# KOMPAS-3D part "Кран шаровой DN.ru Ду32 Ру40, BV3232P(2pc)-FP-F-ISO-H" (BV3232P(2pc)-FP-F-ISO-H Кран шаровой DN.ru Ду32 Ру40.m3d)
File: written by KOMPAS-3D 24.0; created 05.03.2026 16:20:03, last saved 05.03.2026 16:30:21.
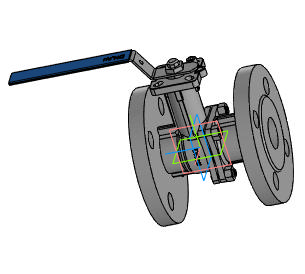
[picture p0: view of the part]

Document properties: Автор: R2D2; Полное имя файла: BV3232P(2pc)-FP-F-ISO-H Кран шаровой DN.ru Ду32 Ру40.cdw

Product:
- Part/product: Кран шаровой DN.ru Ду32 Ру40  | designation BV3232P(2pc)-FP-F-ISO-H
    Масса: 5.17
    Раздел спецификации: Прочие изделия
    Форматы листов документа: A2
    Примечание: D160-22132

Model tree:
1. Операция без истории:1

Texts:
  BV3232P(2pc)-FP-F-ISO-H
